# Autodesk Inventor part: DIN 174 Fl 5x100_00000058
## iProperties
Created: 2006-03
Part Number: DIN 174 Fl 5x100_00000058
Material: Default
Document SubType Name: Modeling
Designer: Carlo
Stock Number: DIN 174 Fl 5x100
Mass: 773.849 g
Surface Area: 3260.58 cm^2
Volume: 773.849 cm^3
Density: 1 g/cm^3
G_L: 1547.896 mm
G_W: 5.000 mm
G_H: 100.000 mm
AFG_Item: 100 x 5
CSToolsMass: 1.0
CSToolsVolume: 773849.0
CSToolsArea: 3261.0
Author: Carlo
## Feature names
1. AFG_Detailed_DIN 174 Fl 5x100_00000058 [Extrusion]
2. AFG_Simplified_DIN 174 Fl 5x100_00000058 [Extrusion]
3. AFG_StartExtrusion_1 [Extrusion]
4. AFG_StartExtrusion_2 [Extrusion]
5. AFG_EndExtrusion_1 [Extrusion]
6. AFG_EndExtrusion_2 [Extrusion]
